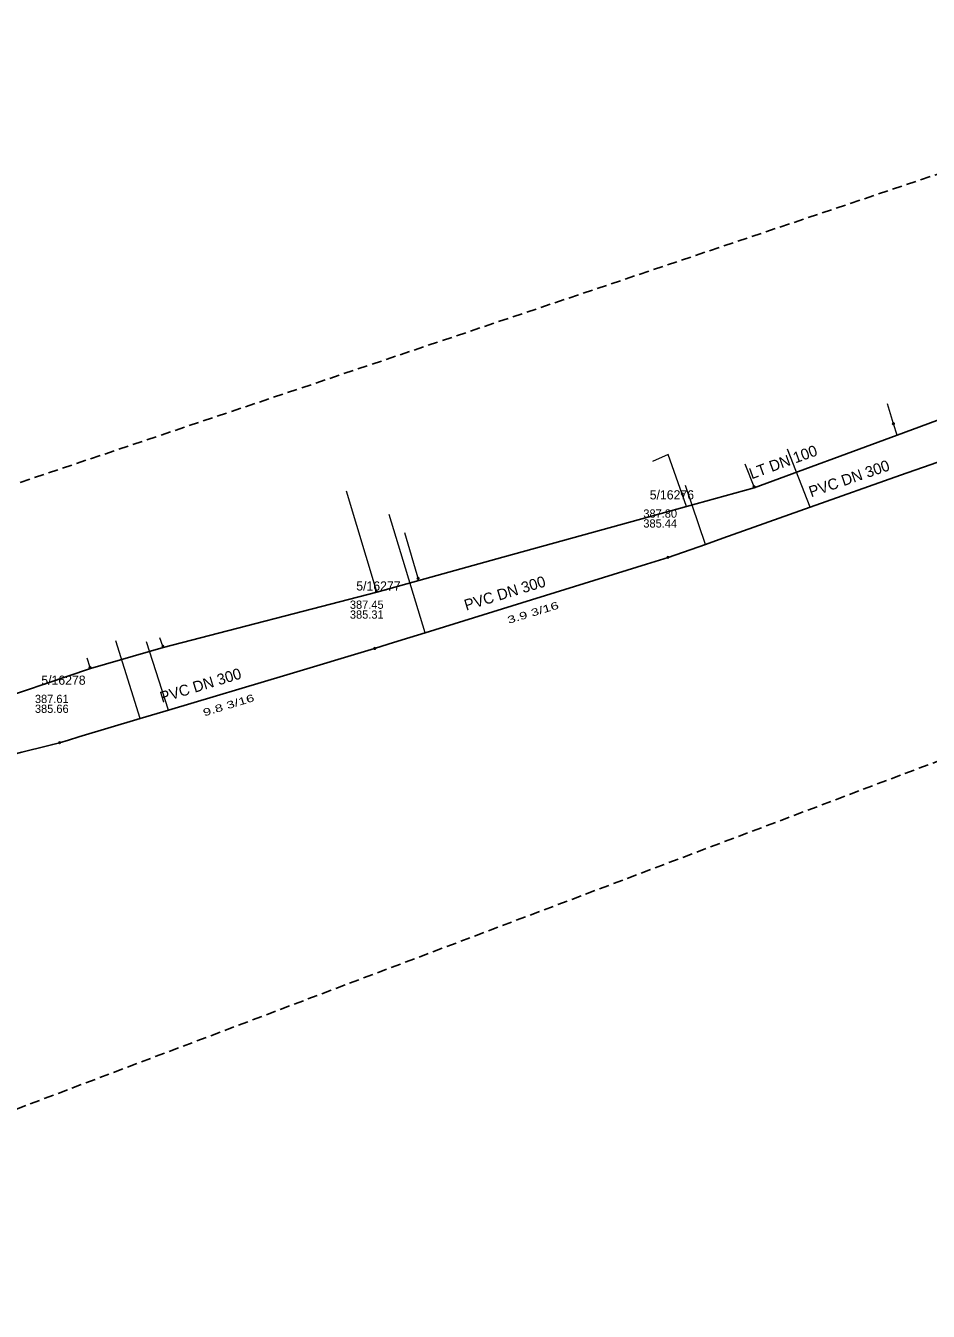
# Model space of a CAD drawing. Extents: x -772855 to -772151, y -1033136 to -1032581.
# Drawn here: x -772696.6 to -772598, y -1033111.6 to -1032971.2 of the extents above; entities that cross this region are included whole.
import ezdxf

# ---------------------------------------------------------------- set-up
doc = ezdxf.new("R2010")
doc.units = 0
doc.header["$LTSCALE"] = 0.36
doc.header["$PDMODE"] = 32
doc.header["$PDSIZE"] = 0.18
doc.linetypes.add('MEDIUM_DASHED', pattern=[4.5, 3, -1.5])
for name, color, linetype in [('15', 7, 'Continuous'), ('17', 7, 'Continuous'), ('3', 7, 'Continuous'), ('4', 7, 'Continuous'), ('5', 7, 'Continuous'), ('56', 7, 'Continuous')]:
    doc.layers.add(name, color=color, linetype=linetype)
for name, color, linetype, lineweight in [('16', 7, 'Continuous', 25), ('2', 7, 'Continuous', 25), ('57', 7, 'Continuous', 13), ('58', 7, 'Continuous', 13), ('62', 7, 'MEDIUM_DASHED', 25)]:
    doc.layers.add(name, color=color, linetype=linetype, lineweight=lineweight)

msp = doc.modelspace()

# ---------------------------------------------------------------- linework, layer by layer
at = {"layer": '15'}
for p in [(-772601.85, -1033014.65), (-772617.059, -1033021.527), (-772624.9, -1033022.329), (-772653.728, -1033031.525), (-772658.286, -1033032.91), (-772681.582, -1033038.95), (-772689.541, -1033041.266)]:
    msp.add_point(p, dxfattribs=at)
at = {"layer": '16'}
msp.add_lwpolyline([(-772814.16, -1033054.64), (-772810.644, -1033054.504), (-772809.916, -1033056.879), (-772782.647, -1033061.241), (-772772.228, -1033059.397), (-772751.464, -1033056.116), (-772726.636, -1033051.157), (-772708.291, -1033047.221), (-772701.557, -1033045.436), (-772689.504, -1033041.381), (-772681.554, -1033039.089), (-772658.252, -1033033.032), (-772645.127, -1033029.408), (-772624.441, -1033023.695), (-772617.034, -1033021.649), (-772601.451, -1033015.905), (-772591.094, -1033012.087)], dxfattribs=at)
at = {"layer": '2'}
for points in [[(-772583.257, -1033013.976), (-772592.248, -1033017.153), (-772597.845, -1033019.131), (-772601.075, -1033020.273), (-772610.92, -1033023.751), (-772620.479, -1033027.13), (-772622.362, -1033027.823), (-772626.45, -1033029.24)], [(-772626.45, -1033029.24), (-772628.8, -1033029.97), (-772634.566, -1033031.761), (-772646.63, -1033035.508), (-772652.974, -1033037.479), (-772655.485, -1033038.259), (-772656.991, -1033038.727), (-772658.48, -1033039.19)], [(-772658.48, -1033039.19), (-772668.05, -1033042.054), (-772680.981, -1033045.924), (-772684.065, -1033046.838), (-772690.759, -1033048.851), (-772691.898, -1033049.192), (-772692.86, -1033049.48)], [(-772692.86, -1033049.48), (-772693.61, -1033049.67), (-772694.185, -1033049.816), (-772696.976, -1033050.523), (-772703.053, -1033052.064), (-772704.442, -1033052.416), (-772708.809, -1033053.523), (-772713.775, -1033054.782), (-772716.498, -1033055.473), (-772719.378, -1033056.203), (-772725.873, -1033057.85), (-772726.255, -1033057.947), (-772726.78, -1033058.08)]]:
    msp.add_lwpolyline(points, dxfattribs=at)
at = {"layer": '4'}
for p in [(-772626.449, -1033029.239), (-772658.48, -1033039.19), (-772692.86, -1033049.48)]:
    msp.add_point(p, dxfattribs=at)
at = {"layer": '57'}
for p, q in [((-772610.92, -1033023.751), (-772613.4, -1033017.43)), ((-772622.362, -1033027.823), (-772624.56, -1033021.39)), ((-772652.974, -1033037.479), (-772656.9, -1033024.56)), ((-772684.065, -1033046.838), (-772686.72, -1033038.37)), ((-772680.981, -1033045.924), (-772683.39, -1033038.47))]:
    msp.add_line(p, q, dxfattribs=at)
at = {"layer": '58'}
msp.add_line((-772653.658, -1033031.764), (-772655.187, -1033026.572), dxfattribs=at)
for points in [[(-772601.451, -1033015.905), (-772601.85, -1033014.65), (-772602.49, -1033012.46)], [(-772624.441, -1033023.695), (-772624.9, -1033022.33), (-772626.45, -1033018.01), (-772628.15, -1033018.77)], [(-772617.034, -1033021.65), (-772617.059, -1033021.528), (-772618.028, -1033019.073)], [(-772658.252, -1033033.033), (-772658.286, -1033032.91), (-772661.535, -1033022.001)], [(-772681.555, -1033039.089), (-772681.582, -1033038.95), (-772681.935, -1033038.029)], [(-772689.504, -1033041.381), (-772689.541, -1033041.266), (-772689.853, -1033040.261)]]:
    msp.add_lwpolyline(points, dxfattribs=at)
at = {"layer": '62'}
msp.add_lwpolyline([(-772807.858, -1033073.22), (-772807.858, -1033073.204), (-772761.644, -1033042.737), (-772462.077, -1032942.017), (-772241.248, -1032806.814), (-772216.072, -1032836.7), (-772367.717, -1032964.854), (-772756.015, -1033111.568)], close=True, dxfattribs=at)

# ---------------------------------------------------------------- texts
at = {"layer": '17'}
msp.add_text('LT DN 100 ', height=1.2, rotation=20, dxfattribs=at).set_placement((-772617.325, -1033020.72))
at = {"layer": '3'}
for rotation, p in [(19, (-772610.834, -1033022.69)), (17, (-772648.484, -1033035.067)), (17, (-772681.697, -1033045.124))]:
    msp.add_text('PVC DN 300', height=1.2, rotation=rotation, dxfattribs=at).set_placement(p)
at = {"layer": '3', "width": 1.5}
for s, p in [('3.9 3/16 ', (-772643.848, -1033036.503)), ('9.8 3/16 ', (-772677.076, -1033046.608))]:
    msp.add_text(s, height=0.8, rotation=17, dxfattribs=at).set_placement(p)
at = {"layer": '5'}
for s, p in [('5/16276', (-772628.45, -1033022.912)), ('5/16277', (-772660.48, -1033032.861)), ('5/16278', (-772694.86, -1033043.151))]:
    msp.add_text(s, height=1, dxfattribs=at).set_placement(p)
at = {"layer": '56'}
for s, p in [('387.80', (-772629.148, -1033024.907)), ('385.44', (-772629.148, -1033025.984)), ('387.45', (-772661.178, -1033034.857)), ('385.31', (-772661.178, -1033035.934)), ('387.61', (-772695.558, -1033045.147)), ('385.66', (-772695.558, -1033046.224))]:
    msp.add_text(s, height=0.9, dxfattribs=at).set_placement(p)

doc.saveas('drawing.dxf')
